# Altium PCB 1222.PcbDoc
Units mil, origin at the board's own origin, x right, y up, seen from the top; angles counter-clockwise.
Board outline 6000 x 4000 mil, 2 copper layers (Top Layer, Bottom Layer); 138 components, 72 nets, 357 pads, 4 vias.
Unrouted connection lines stored in the file: 22.
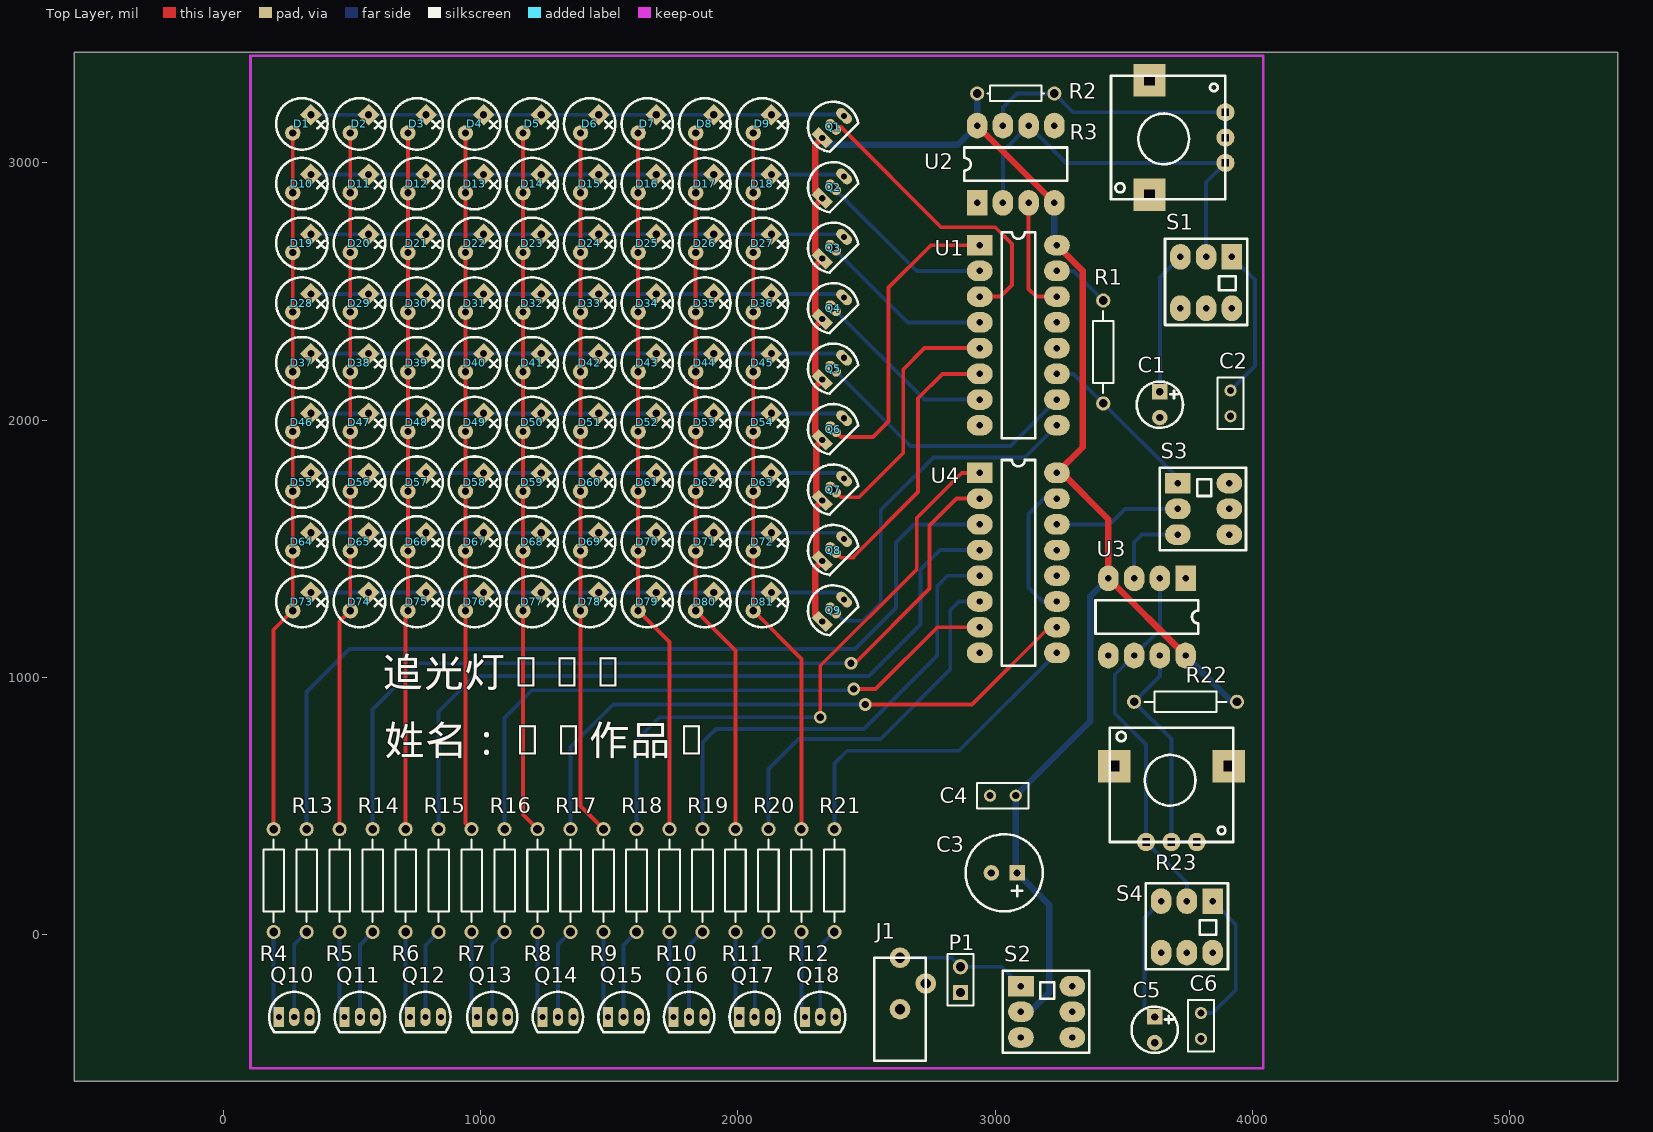
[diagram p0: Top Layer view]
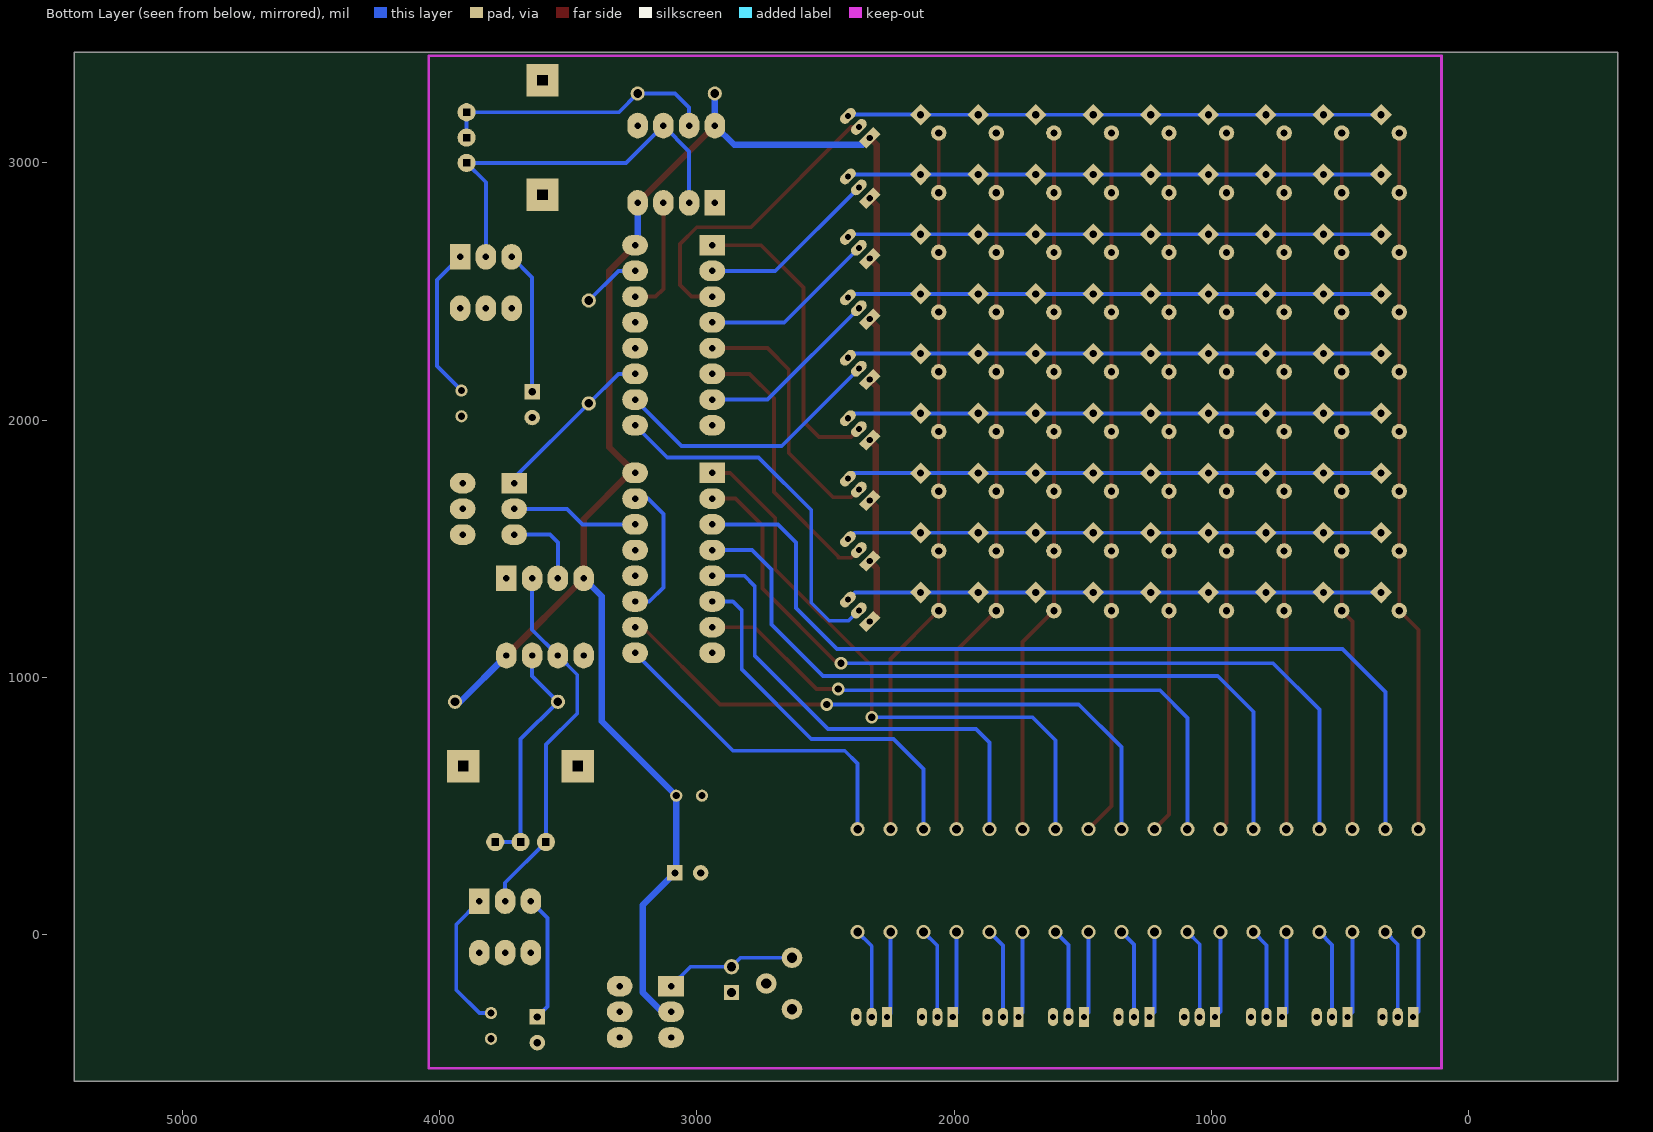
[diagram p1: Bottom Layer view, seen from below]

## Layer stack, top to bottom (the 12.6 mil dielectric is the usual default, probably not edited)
Top Solder: solder mask 0.4, Solder Resist, Dk 3.5
Top Layer: signal copper 1.4
Dielectric 1: dielectric 12.6, FR-4, Dk 4.8
Bottom Layer: signal copper 1.4
Bottom Solder: solder mask 0.4, Solder Resist, Dk 3.5

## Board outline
-580,-570 5420,-570 5420,3430 -580,3430

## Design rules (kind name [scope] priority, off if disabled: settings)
Clearance [All] p1: gap=10
PolygonConnect [All] p1: connectstyle=Relief reliefconductorwidth=10 reliefentries=4 polygonreliefangle="90 Angle" airgapwidth=10
RoutingVias [All] p1: holewidth=28 width=50 viastyle="Through Hole" minholewidth=28 minwidth=50 maxholewidth=28 maxwidth=50
SolderMaskExpansion [All] p1: expansion=4
Width GND [InNet('GND')] p1: maxlimit=25 minlimit=10 preferedwidth=25
Width VCC [InNet('+5V')] p2: maxlimit=25 minlimit=10 preferedwidth=25
Width [All] p3: maxlimit=15 minlimit=10 preferedwidth=15
30 further rules are at their usual default settings.

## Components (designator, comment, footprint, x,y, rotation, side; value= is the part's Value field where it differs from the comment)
C1 "Cap Pol2" 1uF电容器 3640,2110 r270 top
C2 "Cap" RAD-0.1 3915,2065 r270 top
C3 "Cap Pol2" 220uF电容 3085,240 r180 top
C4 "Cap" RAD-0.1 3030,540 r0 top
C5 "Cap Pol2" 1uF电容器 3620,-320 r270 top
C6 "Cap" RAD-0.1 3800,-355 r270 top
D1 "LED1" 发光二极管 340,3187.08 r225 top
D2 "LED1" 发光二极管 563.75,3187.08 r225 top
D3 "LED1" 发光二极管 787.5,3187.08 r225 top
D4 "LED1" 发光二极管 1011.25,3187.08 r225 top
D5 "LED1" 发光二极管 1235,3187.08 r225 top
D6 "LED1" 发光二极管 1458.75,3187.08 r225 top
D7 "LED1" 发光二极管 1682.5,3187.08 r225 top
D8 "LED1" 发光二极管 1906.25,3187.08 r225 top
D9 "LED1" 发光二极管 2130,3187.08 r225 top
D10 "LED1" 发光二极管 340,2954.95 r225 top
D11 "LED1" 发光二极管 563.75,2954.95 r225 top
D12 "LED1" 发光二极管 787.5,2954.95 r225 top
D13 "LED1" 发光二极管 1011.25,2954.95 r225 top
D14 "LED1" 发光二极管 1235,2954.95 r225 top
D15 "LED1" 发光二极管 1458.75,2954.95 r225 top
D16 "LED1" 发光二极管 1682.5,2954.95 r225 top
D17 "LED1" 发光二极管 1906.25,2954.95 r225 top
D18 "LED1" 发光二极管 2130,2954.95 r225 top
D19 "LED1" 发光二极管 340,2722.81 r225 top
D20 "LED1" 发光二极管 563.75,2722.81 r225 top
D21 "LED1" 发光二极管 787.5,2722.81 r225 top
D22 "LED1" 发光二极管 1011.25,2722.81 r225 top
D23 "LED1" 发光二极管 1235,2722.81 r225 top
D24 "LED1" 发光二极管 1458.75,2722.81 r225 top
D25 "LED1" 发光二极管 1682.5,2722.81 r225 top
D26 "LED1" 发光二极管 1906.25,2722.81 r225 top
D27 "LED1" 发光二极管 2130,2722.81 r225 top
D28 "LED1" 发光二极管 340,2490.68 r225 top
D29 "LED1" 发光二极管 563.75,2490.68 r225 top
D30 "LED1" 发光二极管 787.5,2490.68 r225 top
D31 "LED1" 发光二极管 1011.25,2490.68 r225 top
D32 "LED1" 发光二极管 1235,2490.68 r225 top
D33 "LED1" 发光二极管 1458.75,2490.68 r225 top
D34 "LED1" 发光二极管 1682.5,2490.68 r225 top
D35 "LED1" 发光二极管 1906.25,2490.68 r225 top
D36 "LED1" 发光二极管 2130,2490.68 r225 top
D37 "LED1" 发光二极管 340,2258.54 r225 top
D38 "LED1" 发光二极管 563.75,2258.54 r225 top
D39 "LED1" 发光二极管 787.5,2258.54 r225 top
D40 "LED1" 发光二极管 1011.25,2258.54 r225 top
D41 "LED1" 发光二极管 1235,2258.54 r225 top
D42 "LED1" 发光二极管 1458.75,2258.54 r225 top
D43 "LED1" 发光二极管 1682.5,2258.54 r225 top
D44 "LED1" 发光二极管 1906.25,2258.54 r225 top
D45 "LED1" 发光二极管 2130,2258.54 r225 top
D46 "LED1" 发光二极管 340,2026.41 r225 top
D47 "LED1" 发光二极管 563.75,2026.41 r225 top
D48 "LED1" 发光二极管 787.5,2026.41 r225 top
D49 "LED1" 发光二极管 1011.25,2026.41 r225 top
D50 "LED1" 发光二极管 1235,2026.41 r225 top
D51 "LED1" 发光二极管 1458.75,2026.41 r225 top
D52 "LED1" 发光二极管 1682.5,2026.41 r225 top
D53 "LED1" 发光二极管 1906.25,2026.41 r225 top
D54 "LED1" 发光二极管 2130,2026.41 r225 top
D55 "LED1" 发光二极管 340,1794.27 r225 top
D56 "LED1" 发光二极管 563.75,1794.27 r225 top
D57 "LED1" 发光二极管 787.5,1794.27 r225 top
D58 "LED1" 发光二极管 1011.25,1794.27 r225 top
D59 "LED1" 发光二极管 1235,1794.27 r225 top
D60 "LED1" 发光二极管 1458.75,1794.27 r225 top
D61 "LED1" 发光二极管 1682.5,1794.27 r225 top
D62 "LED1" 发光二极管 1906.25,1794.27 r225 top
D63 "LED1" 发光二极管 2130,1794.27 r225 top
D64 "LED1" 发光二极管 340,1562.14 r225 top
D65 "LED1" 发光二极管 563.75,1562.14 r225 top
D66 "LED1" 发光二极管 787.5,1562.14 r225 top
D67 "LED1" 发光二极管 1011.25,1562.14 r225 top
D68 "LED1" 发光二极管 1235,1562.14 r225 top
D69 "LED1" 发光二极管 1458.75,1562.14 r225 top
D70 "LED1" 发光二极管 1682.5,1562.14 r225 top
D71 "LED1" 发光二极管 1906.25,1562.14 r225 top
D72 "LED1" 发光二极管 2130,1562.14 r225 top
D73 "LED1" 发光二极管 340,1330 r225 top
D74 "LED1" 发光二极管 563.75,1330 r225 top
D75 "LED1" 发光二极管 787.5,1330 r225 top
D76 "LED1" 发光二极管 1011.25,1330 r225 top
D77 "LED1" 发光二极管 1235,1330 r225 top
D78 "LED1" 发光二极管 1458.75,1330 r225 top
D79 "LED1" 发光二极管 1682.5,1330 r225 top
D80 "LED1" 发光二极管 1906.25,1330 r225 top
D81 "LED1" 发光二极管 2130,1330 r225 top
J1 "PWR2.5" 电源接口 2620,-290 r90 top
P1 "MHDR1X2" HDR1X2 2865,-225 r90 top
Q1 "NPN" TO-92-3_L4.9-W3.7-P1.27-L 2370,3140 r45 top
Q2 "NPN" TO-92-3_L4.9-W3.7-P1.27-L 2370,2905 r45 top
Q3 "NPN" TO-92-3_L4.9-W3.7-P1.27-L 2370,2670 r45 top
Q4 "NPN" TO-92-3_L4.9-W3.7-P1.27-L 2370,2435 r45 top
Q5 "NPN" TO-92-3_L4.9-W3.7-P1.27-L 2370,2200 r45 top
Q6 "NPN" TO-92-3_L4.9-W3.7-P1.27-L 2370,1965 r45 top
Q7 "NPN" TO-92-3_L4.9-W3.7-P1.27-L 2370,1730 r45 top
Q8 "NPN" TO-92-3_L4.9-W3.7-P1.27-L 2370,1495 r45 top
Q9 "NPN" TO-92-3_L4.9-W3.7-P1.27-L 2370,1260 r45 top
Q10 "NPN" TO-92-3_L4.9-W3.7-P1.27-L 275,-320 r0 top
Q11 "NPN" TO-92-3_L4.9-W3.7-P1.27-L 530,-320 r0 top
Q12 "NPN" TO-92-3_L4.9-W3.7-P1.27-L 785,-320 r0 top
Q13 "NPN" TO-92-3_L4.9-W3.7-P1.27-L 1045,-320 r0 top
Q14 "NPN" TO-92-3_L4.9-W3.7-P1.27-L 1300,-320 r0 top
Q15 "NPN" TO-92-3_L4.9-W3.7-P1.27-L 1555,-320 r0 top
Q16 "NPN" TO-92-3_L4.9-W3.7-P1.27-L 1810,-320 r0 top
Q17 "NPN" TO-92-3_L4.9-W3.7-P1.27-L 2065,-320 r0 top
Q18 "NPN" TO-92-3_L4.9-W3.7-P1.27-L 2320,-320 r0 top
R1 "Res2" AXIAL-0.4 3420,2265 r270 top
R2 "Res2" AXIAL-0.3 3080,3270 r0 top
R3 "RPot" 立式手柄电位器 3895,3098.43 r90 top
R4 "Res2" AXIAL-0.4 195,210 r90 top
R5 "Res2" AXIAL-0.4 451.47,210 r90 top
R6 "Res2" AXIAL-0.4 707.94,210 r90 top
R7 "Res2" AXIAL-0.4 964.41,210 r90 top
R8 "Res2" AXIAL-0.4 1220.88,210 r90 top
R9 "Res2" AXIAL-0.4 1477.35,210 r90 top
R10 "Res2" AXIAL-0.4 1733.82,210 r90 top
R11 "Res2" AXIAL-0.4 1990.29,210 r90 top
R12 "Res2" AXIAL-0.4 2246.76,210 r90 top
R13 "Res2" AXIAL-0.4 323.24,210 r90 top
R14 "Res2" AXIAL-0.4 579.71,210 r90 top
R15 "Res2" AXIAL-0.4 836.18,210 r90 top
R16 "Res2" AXIAL-0.4 1092.65,210 r90 top
R17 "Res2" AXIAL-0.4 1349.12,210 r90 top
R18 "Res2" AXIAL-0.4 1605.59,210 r90 top
R19 "Res2" AXIAL-0.4 1862.06,210 r90 top
R20 "Res2" AXIAL-0.4 2118.53,210 r90 top
R21 "Res2" AXIAL-0.4 2375,210 r90 top
R22 "Res2" AXIAL-0.4 3740,905 r180 top
R23 "RPot" 立式手柄电位器 3685,360 r0 top
S1 "SW-SPDT" KEY-6 3920,2635 r270 top
S2 "SW-SPST" KEY-6 3100,-200 r0 top
S3 "SW-SPDT" KEY-6 3710,1755 r0 top
S4 "SW-SPDT" KEY-6 3845,130 r270 top
U1 "CD4017BCN" cd4017 2940,2680 r0 top
U2 "NE555N" NE555 2930,2845 r90 top
U3 "NE555N" NE555 3740,1385 r270 top
U4 "CD4017BCN" cd4017 2940,1795 r0 top

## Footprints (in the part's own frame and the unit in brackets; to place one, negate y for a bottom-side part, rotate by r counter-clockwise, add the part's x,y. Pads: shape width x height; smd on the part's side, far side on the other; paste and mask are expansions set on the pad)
1uF电容器 [mil]
  rect 60x60 hole 28: 1(0,0)
  round 60 hole 28: 2(100,0)
  silkscreen extent -40,-90 140,90
220uF电容 [mil]
  rect 60x60 hole 28: 1(0,0)
  round 60 hole 28: 2(100,0)
  silkscreen extent -100,-150 200,150
AXIAL-0.3 [mm] "Axial Device, Thru-Hole; 2 Leads; 0.3 in Pin Spacing"
  round 1.4 hole 0.85: 1(-3.81,0) 2(3.81,0)
  silkscreen extent -2.77,-0.76 2.77,0.76
AXIAL-0.4 [mm] "Axial Device, Thru-Hole; 2 Leads; 0.4 in Pin Spacing"
  round 1.4 hole 0.85: 1(-5.08,0) 2(5.08,0)
  silkscreen extent -4.06,-1.02 4.06,1.02
cd4017 [mil]
  rect 100x80 hole 25: 1(0,0)
  oval 100x80 hole 25: 2(0,-100) 3(0,-200) 4(0,-300) 5(0,-400) 6(0,-500) 7(0,-600) 8(0,-700) 9(300,-700) 10(300,-600) 11(300,-500) 12(300,-400) 13(300,-300) 14(300,-200) 15(300,-100) 16(300,0)
  silkscreen extent 85,-750 215,50
HDR1X2 [mm] "Connector; Header; 2 Position"
  rect 1.5x1.5 hole 0.9: 1(0,0)
  round 1.5 hole 0.9: 2(2.54,0)
  silkscreen extent -1.27,-1.27 3.81,1.27
KEY-6 [mil]
  rect 100x80 hole 25: 1(0,0)
  oval 100x80 hole 25: 2(0,-100) 3(0,-200) 4(200,-200) 5(200,-100) 6(200,0)
  silkscreen extent -70,-260 265,60
NE555 [mil]
  rect 100x80 hole 25: 1(0,0)
  oval 100x80 hole 25: 2(0,-100) 3(0,-200) 4(0,-300) 5(300,-300) 6(300,-200) 7(300,-100) 8(300,0)
  silkscreen extent 85,-350 215,50
RAD-0.1 [mm] "Radial Cap, Thru-Hole; 2 Leads; 0.1 in Pin Spacing"
  round 1.2 hole 0.7: 1(-1.27,0) 2(1.27,0)
  silkscreen extent -2.54,-1.27 2.54,1.27
TO-92-3_L4.9-W3.7-P1.27-L [mm]
  rect 1x2 hole 0.6: 1(-1.524,0)
  oval 1x1.8 hole 0.6: 2(0,0) 3(1.524,0)
  silkscreen extent -2.48,-1.5 2.48,2.48
发光二极管 [mil]
  rect 60x60 hole 28: 1(0,0)
  round 60 hole 28: 2(100,0)
  silkscreen extent -50,-100 150,100
电源接口 [mil]
  round 80 hole 40: 1(200,-10) 2(0,-10) 3(100,-110)
  silkscreen extent -200,-110 200,90
立式手柄电位器 [mm]
  round 1.8 hole 0.7 square: 1(-2.5,0) 2(2.5,0) 3(0,0)
  rect 3.2x3.2 hole 1 square: 4(-5.65,7.5) 5(5.65,7.5)
  silkscreen extent -6.1,0 6.1,11.3

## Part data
C1 C3 C5: "Polarized Capacitor (Axial)"
C2 C4 C6: "Capacitor"
D1 D2 D3 D4 D5 D6 D7 D8 D9 D10 D11 D12 D13 D14 D15 D16 D17 D18 D19 D20 D21 D22 D23 D24 D25 D26 D27 D28 D29 D30 D31 D32 D33 D34 D35 D36 D37 D38 D39 D40 D41 D42 D43 D44 D45 D46 D47 D48 D49 D50 D51 D52 D53 D54 D55 D56 D57 D58 D59 D60 D61 D62 D63 D64 D65 D66 D67 D68 D69 D70 D71 D72 D73 D74 D75 D76 D77 D78 D79 D80 D81: "Typical RED GaAs LED"
J1: "Low Voltage Power Supply Connector"
P1: "Header, 2-Pin"
Q1 Q2 Q3 Q4 Q5 Q6 Q7 Q8 Q9 Q10 Q11 Q12 Q13 Q14 Q15 Q16 Q17 Q18: "NPN Bipolar Transistor"
R1 R2 R4 R5 R6 R7 R8 R9 R10 R11 R12 R13 R14 R15 R16 R17 R18 R19 R20 R21 R22: "Resistor"
R3 R23: "Potentiometer"
S1 S3 S4: "SPDT Subminiature Toggle Switch, Right Angle Mounting, Vertical Actuation"
S2: "Single-Pole, Single-Throw Switch"
U1 U4: "Decade Counter/Divider with 10 Decoded Outputs"
U2 U3: "General-Purpose Single Bipolar Timer"

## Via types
v1: diameter 50, hole 28, Top Layer to Bottom Layer, 4 vias

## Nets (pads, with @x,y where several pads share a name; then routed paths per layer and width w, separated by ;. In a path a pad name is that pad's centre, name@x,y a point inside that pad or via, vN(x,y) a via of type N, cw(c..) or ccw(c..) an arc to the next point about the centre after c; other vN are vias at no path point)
+5V: C3.1 C4.2 Q1.1 Q2.1 Q3.1 Q4.1 Q5.1 Q6.1 Q7.1 Q8.1 Q9.1 R2.1 R22.1 S2.2 U1.16 U2.4 U2.8 U3.4 U3.8 U4.16 | length 7543
  Top Layer w25: Q9.1 2300,1245.15 2300,1425 Q8.1 2305,1475.15 2305,1665 Q7.1 2305,1710.15 2305,1900 Q6.1 2300,1950.15 2300,2130 Q5.1 2300,2185.15 2300,2365 Q4.1 2300,2420.15 2300,2600 Q3.1 2300,2655.15 2300,2835 Q2.1 2300,2890.15 2300,3070 Q1.1 ; U2.8 U2.4 ; U1.16 3340,2580 3340,1895 U4.16 3260,1795 3440,1615 U3.4 U3.8
  Bottom Layer w25: Q1.1 2355.15,3070 2855,3070 U2.8 R2.1 ; S2.2 3135,-300 3210,-225 3210,115 C3.1 3080,245 C4.2 3370,830 3370,1315 U3.4 ; U2.4 3230,2690 U1.16 ; U3.8 3920,905 R22.1
GND: C1.2 C2.2 C3.2 C4.1 C5.2 C6.2 J1.2 P1.1 Q10.3 Q11.3 Q12.3 Q13.3 Q14.3 Q15.3 Q16.3 Q17.3 Q18.3 U1.8 U1.13 U2.1 U3.1 U4.8 U4.13
H1: Q1.2 U1.3 | length 1187.1
  Top Layer w15: Q1.2 2400,3140 2790,2750 3000,2750 3065,2685 3065,2525 3020,2480 U1.3
H2: Q2.2 U1.2 | length 704.6
  Bottom Layer w15: Q2.2 2695,2580 U1.2
H3: Q3.2 U1.4 | length 690.1
  Bottom Layer w15: Q3.2 2660,2380 U1.4
H4: Q4.2 U1.7 | length 717
  Bottom Layer w15: Q4.2 2725,2080 U1.7
H5: Q5.2 U1.10 | length 1068.8
  Bottom Layer w15: Q5.2 2670,1900 3060,1900 U1.10
H6: Q6.2 U1.1 | length 1195.6
  Top Layer w15: Q6.2 2400,1935 2525,1935 2585,1995 2585,2515 2750,2680 U1.1
H7: Q7.2 U1.5 | length 1013.1
  Top Layer w15: Q7.2 2400,1700 2470,1700 2642.5,1872.5 2642.5,2197.5 2725,2280 U1.5
H8: Q8.2 U1.6 | length 1095.3
  Top Layer w15: Q8.2 2400,1465 2450,1465 2450,1470 2700,1720 2700,2085 2795,2180 U1.6
H9: Q9.2 U1.9 | length 1412.3
  Bottom Layer w15: Q9.2 2410,1220 2485,1220 2555,1290 2555,1650 2760,1855 3115,1855 U1.9
L1: R13.2 U4.3 | length 3569.3
  Bottom Layer w15: R13.2 323.24,943.24 490,1110 2455,1110 2615,1270 2615,1525 2685,1595 U4.3
L2: R14.2 U4.2 | length 3308.3
  Top Layer w15: v1(2440,1055) 2455,1055 2745,1345 2745,1590 2850,1695 U4.2
  Bottom Layer w15: R14.2 579.71,874.71 760,1055 v1(2440,1055)
L3: R15.2 U4.4 | length 2946.4
  Bottom Layer w15: R15.2 836.18,866.18 975,1005 2510,1005 2710,1205 2710,1420 2785,1495 U4.4
L4: R16.2 U4.7 | length 2435.9
  Top Layer w15: v1(2450,955) 2535,955 2775,1195 U4.7
  Bottom Layer w15: R16.2 1092.65,842.65 1200,950 2450,950 2445,955 v1(2450,955)
L5: R17.2 U4.10 | length 2403
  Top Layer w15: v1(2495,895) 2910,895 3210,1195 U4.10
  Bottom Layer w15: R17.2 1349.12,729.12 1515,895 v1(2495,895)
L6: R18.2 U4.1 | length 2344.9
  Top Layer w15: v1(2320,845) 2320,1045 2695,1420 2695,1620 2870,1795 U4.1
  Bottom Layer w15: R18.2 1605.59,755.59 1695,845 v1(2320,845)
L7: R19.2 U4.5 | length 1841.5
  Bottom Layer w15: R19.2 1862.06,747.06 1915,800 2490,800 2775,1085 2775,1355 2815,1395 U4.5
L8: R20.2 U4.6 | length 1459.6
  Bottom Layer w15: R20.2 2118.53,643.53 2235,760 2555,760 2825,1030 2825,1260 2860,1295 U4.6
L9: R21.2 U4.9 | length 1298.1
  Bottom Layer w15: R21.2 2375,665 2425,715 2860,715 U4.9
NetC1_1: C1.1 S1.3 | length 558.1
  Bottom Layer w15: C1.1 3640,2555 S1.3
NetC2_1: C2.1 S1.1 | length 596.6
  Bottom Layer w15: C2.1 4010,2210 4010,2545 S1.1
NetC5_1: C5.1 S4.3 | length 493.5
  Bottom Layer w15: C5.1 3580,-280 3580,65 S4.3
NetC6_1: C6.1 S4.1 | length 554.6
  Bottom Layer w15: C6.1 3845,-305 3935,-215 3935,40 S4.1
NetD1_1: D1.1 D2.1 D3.1 D4.1 D5.1 D6.1 D7.1 D8.1 D9.1 Q1.3 | length 2076.1
  Bottom Layer w15: D1.1 D2.1 D3.1 D4.1 D5.1 D6.1 D7.1 D8.1 D9.1 2130,3188.32 2406.53,3188.32 Q1.3
NetD1_2: D1.2 D10.2 D19.2 D28.2 D37.2 D46.2 D55.2 D64.2 D73.2 R4.2 | length 2737.1
  Top Layer w15: R4.2 195,1185 D73.2 D64.2 D55.2 D46.2 D37.2 D28.2 D19.2 D10.2 D1.2
NetD2_2: D2.2 D11.2 D20.2 D29.2 D38.2 D47.2 D56.2 D65.2 D74.2 R5.2 | length 2723.6
  Top Layer w15: R5.2 451.47,1217.72 D74.2 D65.2 D56.2 D47.2 D38.2 D29.2 D20.2 D11.2 D2.2
NetD3_2: D3.2 D12.2 D21.2 D30.2 D39.2 D48.2 D57.2 D66.2 D75.2 R6.2 | length 2710
  Top Layer w15: R6.2 707.94,1250.44 D75.2 D66.2 D57.2 D48.2 D39.2 D30.2 D21.2 D12.2 D3.2
NetD4_2: D4.2 D13.2 D22.2 D31.2 D40.2 D49.2 D58.2 D67.2 D76.2 R7.2 | length 2716.3
  Top Layer w15: D4.2 D13.2 D22.2 D31.2 D40.2 D49.2 D58.2 D67.2 D76.2 940.54,433.87 R7.2
NetD5_2: D5.2 D14.2 D23.2 D32.2 D41.2 D50.2 D59.2 D68.2 D77.2 R8.2 | length 2729.8
  Top Layer w15: D5.2 D14.2 D23.2 D32.2 D41.2 D50.2 D59.2 D68.2 D77.2 1164.29,466.59 R8.2
NetD6_2: D6.2 D15.2 D24.2 D33.2 D42.2 D51.2 D60.2 D69.2 D78.2 R9.2 | length 2743.4
  Top Layer w15: D6.2 D15.2 D24.2 D33.2 D42.2 D51.2 D60.2 D69.2 D78.2 1388.04,499.31 R9.2
NetD7_2: D7.2 D16.2 D25.2 D34.2 D43.2 D52.2 D61.2 D70.2 D79.2 R10.2 | length 2756.9
  Top Layer w15: D7.2 D16.2 D25.2 D34.2 D43.2 D52.2 D61.2 D70.2 D79.2 1733.82,1137.26 R10.2
NetD8_2: D8.2 D17.2 D26.2 D35.2 D44.2 D53.2 D62.2 D71.2 D80.2 R11.2 | length 2770.5
  Top Layer w15: D8.2 D17.2 D26.2 D35.2 D44.2 D53.2 D62.2 D71.2 D80.2 1990.29,1104.54 R11.2
NetD9_2: D9.2 D18.2 D27.2 D36.2 D45.2 D54.2 D63.2 D72.2 D81.2 R12.2 | length 2784
  Top Layer w15: D9.2 D18.2 D27.2 D36.2 D45.2 D54.2 D63.2 D72.2 D81.2 2246.76,1071.82 R12.2
NetD10_1: D10.1 D11.1 D12.1 D13.1 D14.1 D15.1 D16.1 D17.1 D18.1 Q2.3 | length 2075.5
  Bottom Layer w15: D10.1 D11.1 D12.1 D13.1 D14.1 D15.1 D16.1 D17.1 D18.1 2404.9,2954.95 Q2.3
NetD19_1: D19.1 D20.1 D21.1 D22.1 D23.1 D24.1 D25.1 D26.1 D27.1 Q3.3 | length 2076.7
  Bottom Layer w15: D19.1 D21.1 D22.1 D23.1 D26.1 D27.1 2402.04,2722.81 Q3.3
NetD28_1: D28.1 D29.1 D30.1 D31.1 D32.1 D33.1 D34.1 D35.1 D36.1 Q4.3 | length 2077.9
  Bottom Layer w15: D28.1 D29.1 D30.1 D31.1 D32.1 D33.1 D34.1 D35.1 D36.1 2399.18,2490.68 Q4.3
NetD37_1: D37.1 D38.1 D39.1 D40.1 D41.1 D42.1 D43.1 D44.1 D45.1 Q5.3 | length 2079.1
  Bottom Layer w15: D37.1 D39.1 D40.1 D45.1 2396.31,2258.54 Q5.3
NetD46_1: D46.1 D47.1 D48.1 D49.1 D50.1 D51.1 D52.1 D53.1 D54.1 Q6.3 | length 2080.3
  Bottom Layer w15: D46.1 D47.1 D48.1 D49.1 D50.1 D51.1 D52.1 D53.1 D54.1 2393.45,2026.41 Q6.3
NetD55_1: D55.1 D56.1 D57.1 D58.1 D59.1 D60.1 D61.1 D62.1 D63.1 Q7.3 | length 2081.5
  Bottom Layer w15: D55.1 D56.1 D57.1 D60.1 D61.1 D62.1 D63.1 2390.58,1794.27 Q7.3
NetD64_1: D64.1 D65.1 D66.1 D67.1 D68.1 D69.1 D70.1 D71.1 D72.1 Q8.3 | length 2082.7
  Bottom Layer w15: D64.1 D65.1 D66.1 D67.1 D68.1 D69.1 D70.1 D71.1 D72.1 2387.72,1562.14 Q8.3
NetD73_1: D73.1 D74.1 D75.1 D76.1 D77.1 D78.1 D79.1 D80.1 D81.1 Q9.3 | length 2083.8
  Bottom Layer w15: D73.1 D74.1 D75.1 D76.1 D77.1 D78.1 D79.1 D80.1 D81.1 2384.85,1330 Q9.3
NetJ1_1: J1.1 P1.2 S2.1 | length 515.6
  Bottom Layer w15: J1.1 2830,-90 P1.2 3025,-125 S2.1
NetJ1_3: J1.3
NetQ10_1: Q10.1 R4.1 | length 338.3
  Bottom Layer w15: R4.1 195,-300 Q10.1
NetQ10_2: Q10.2 R13.1 | length 350
  Bottom Layer w15: Q10.2 275,-38.24 R13.1
NetQ11_1: Q11.1 R5.1 | length 337.7
  Bottom Layer w15: R5.1 451.47,-301.47 Q11.1
NetQ11_2: Q11.2 R14.1 | length 350.6
  Bottom Layer w15: Q11.2 530,-39.71 R14.1
NetQ12_1: Q12.1 R6.1 | length 337.1
  Bottom Layer w15: R6.1 707.94,-302.94 Q12.1
NetQ12_2: Q12.2 R15.1 | length 351.2
  Bottom Layer w15: Q12.2 785,-41.18 R15.1
NetQ13_1: Q13.1 R7.1 | length 338.5
  Bottom Layer w15: R7.1 964.41,-299.41 Q13.1
NetQ13_2: Q13.2 R16.1 | length 349.7
  Bottom Layer w15: Q13.2 1045,-37.65 R16.1
NetQ14_1: Q14.1 R8.1 | length 337.9
  Bottom Layer w15: R8.1 1220.88,-300.88 Q14.1
NetQ14_2: Q14.2 R17.1 | length 350.3
  Bottom Layer w15: Q14.2 1300,-39.12 R17.1
NetQ15_1: Q15.1 R9.1 | length 337.3
  Bottom Layer w15: R9.1 1477.35,-302.35 Q15.1
NetQ15_2: Q15.2 R18.1 | length 351
  Bottom Layer w15: Q15.2 1555,-40.59 R18.1
NetQ16_1: Q16.1 R10.1 | length 336.7
  Bottom Layer w15: R10.1 1733.82,-303.82 Q16.1
NetQ16_2: Q16.2 R19.1 | length 351.6
  Bottom Layer w15: Q16.2 1810,-42.06 R19.1
NetQ17_1: Q17.1 R11.1 | length 336.1
  Bottom Layer w15: R11.1 1990.29,-305.29 Q17.1
NetQ17_2: Q17.2 R20.1 | length 352.2
  Bottom Layer w15: Q17.2 2065,-43.53 R20.1
NetQ18_1: Q18.1 R12.1 | length 335.5
  Bottom Layer w15: R12.1 2246.76,-306.76 Q18.1
NetQ18_2: Q18.2 R21.1 | length 352.8
  Bottom Layer w15: Q18.2 2320,-45 R21.1
NetR1_1: R1.1 U1.15 | length 227.6
  Bottom Layer w15: U1.15 3305,2580 R1.1
NetR1_2: R1.2 S3.1 U1.11 | length 657.8
  Bottom Layer w15: U1.11 3305,2180 R1.2 3710,1775 S3.1
NetR2_2: R2.2 R3.2 R3.3 U2.7 | length 1086.5
  Bottom Layer w15: U2.7 3030,3215 3085,3270 R2.2 3303.15,3196.85 R3.2 R3.3
NetR3_1: R3.1 S1.2 U2.2 U2.6 | length 1562.5
  Bottom Layer w15: U2.2 3030,3045 U2.6 3275,3000 R3.1 3820,2925 S1.2
NetR22_2: R22.2 R23.2 R23.3 U3.7 | length 924.9
  Bottom Layer w15: U3.7 3640,1005 R22.2 3685,760 R23.3 R23.2
NetR23_1: R23.1 S4.2 U3.2 U3.6 | length 1443.5
  Bottom Layer w15: U3.2 3640,1185 U3.6 3465,1010 3465,860 3586.57,738.43 R23.1 3745,201.57 S4.2
NetS3_2: S3.2 U4.14 | length 494.9
  Bottom Layer w15: U4.14 3445,1595 3505,1655 S3.2
NetS3_3: S3.3 U3.3 | length 322.4
  Bottom Layer w15: U3.3 3540,1525 3570,1555 S3.3
NetU1_14: U1.14 U2.3 | length 457.4
  Top Layer w15: U2.3 3130,2510 3160,2480 U1.14
NetU4_11: U4.11 U4.15 | length 552.6
  Bottom Layer w15: U4.11 3185,1295 3130,1350 3130,1635 3190,1695 U4.15
pads on no net: R3.4 R3.5 R23.4 R23.5 S1.4 S1.5 S1.6 S2.3 S2.4 S2.5 S2.6 S3.4 S3.5 S3.6 S4.4 S4.5 S4.6 U1.12 U2.5 U3.5 U4.12

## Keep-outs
Keep-Out Layer:
  lines w10: 105,-520 105,3417.01 4042.01,3417.01 4042.01,-520 105,-520

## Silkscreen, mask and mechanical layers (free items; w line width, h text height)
Top Overlay:
  text "追光灯PCB" at 620,925 h200
  text "姓名：24作品2" at 625,660 h200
